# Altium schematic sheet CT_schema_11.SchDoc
size 677 x 458 mm
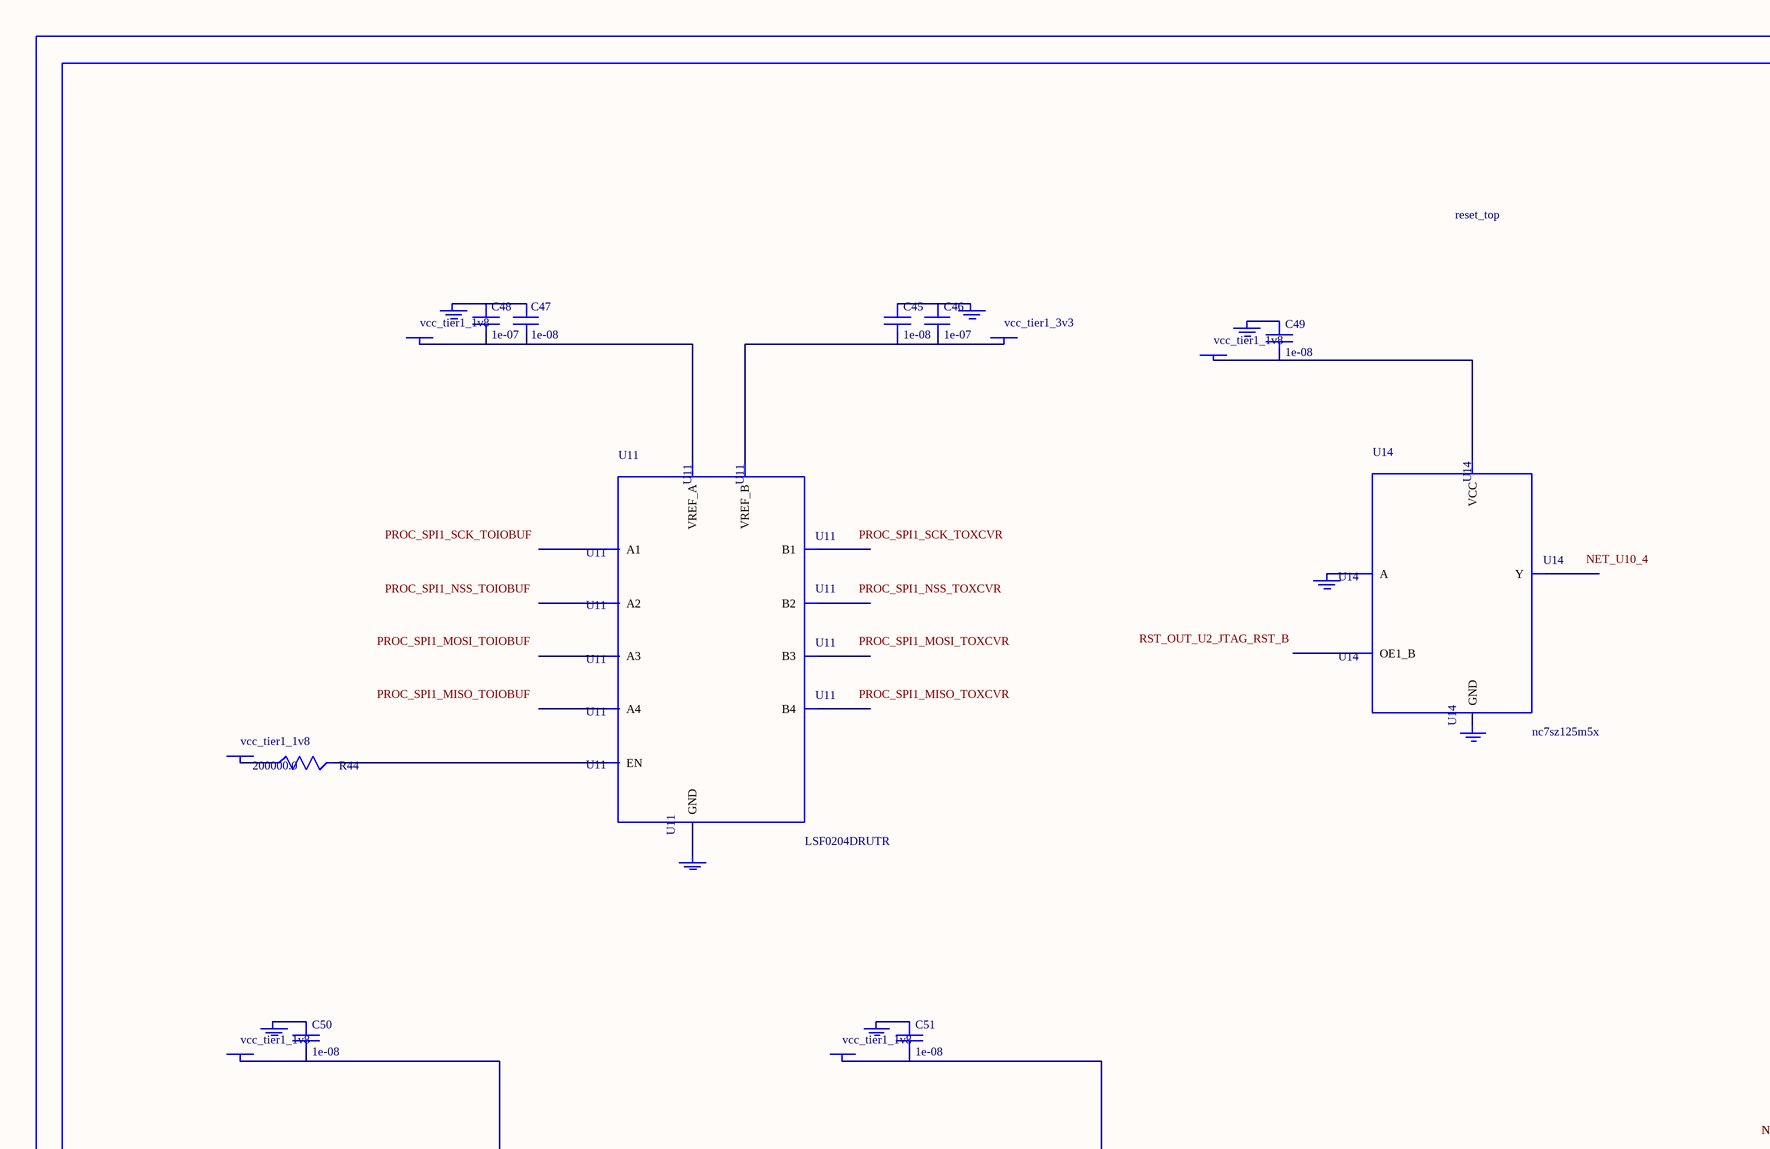
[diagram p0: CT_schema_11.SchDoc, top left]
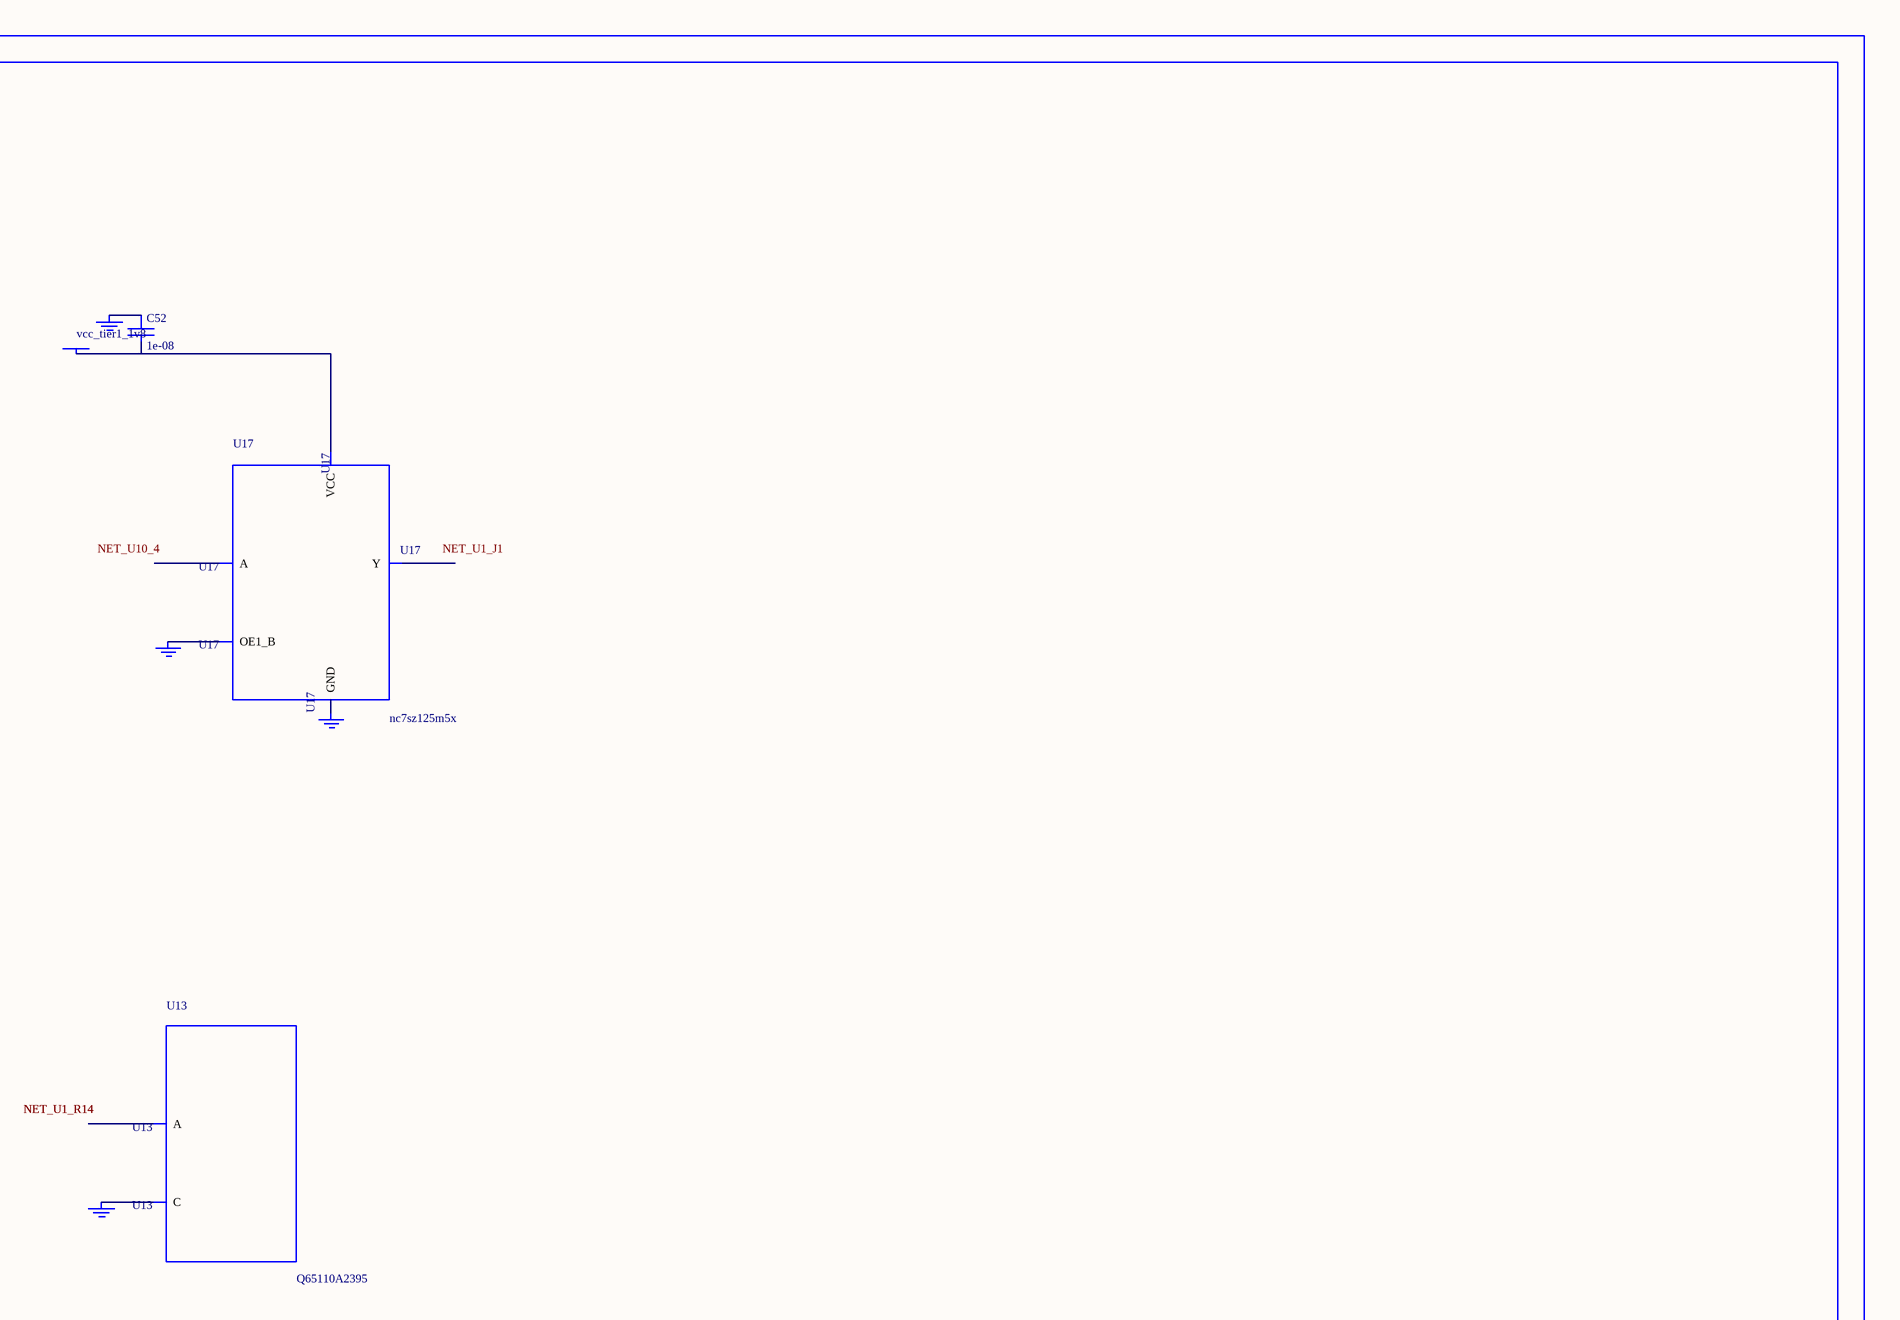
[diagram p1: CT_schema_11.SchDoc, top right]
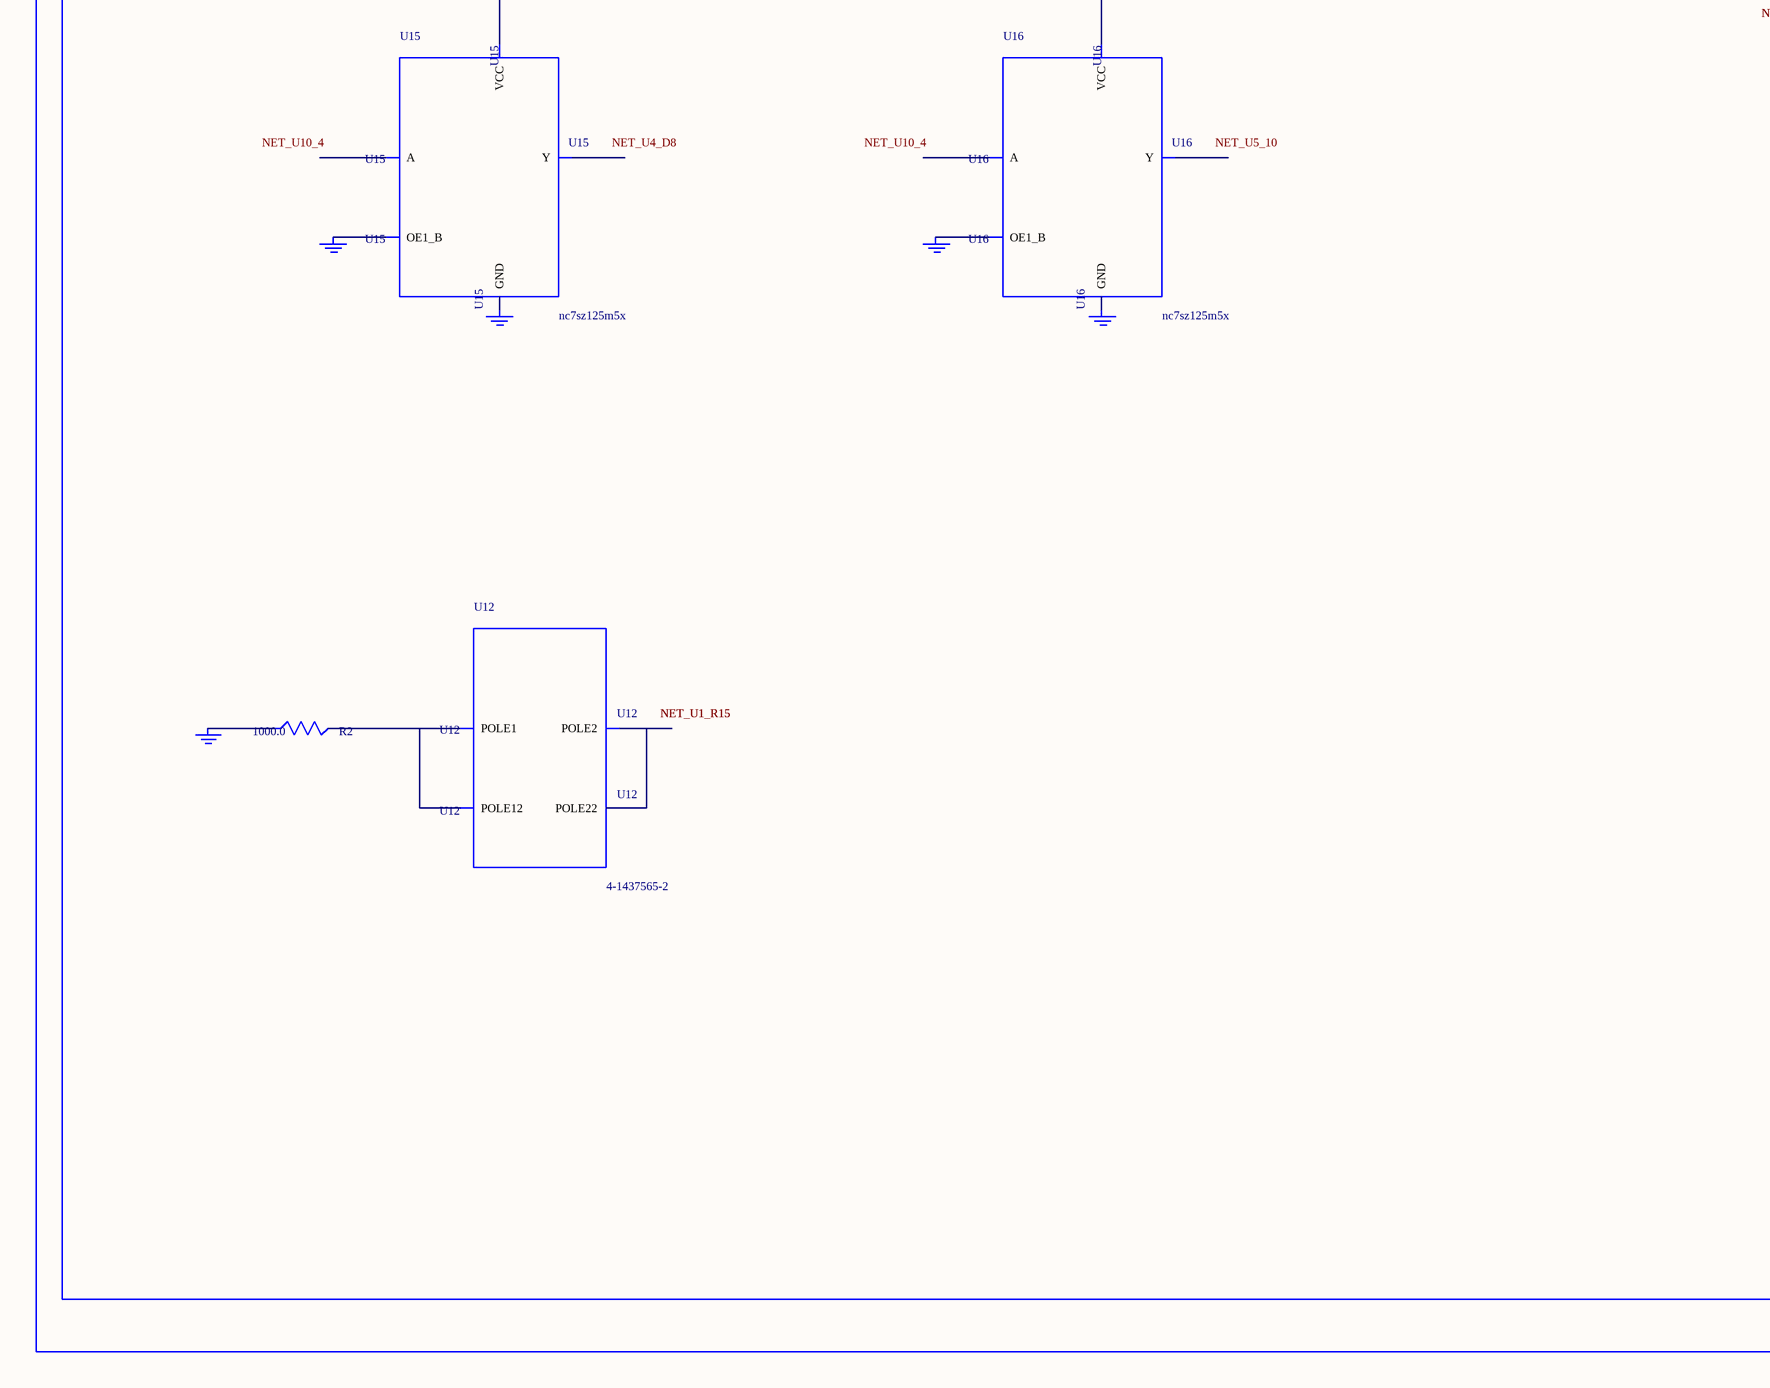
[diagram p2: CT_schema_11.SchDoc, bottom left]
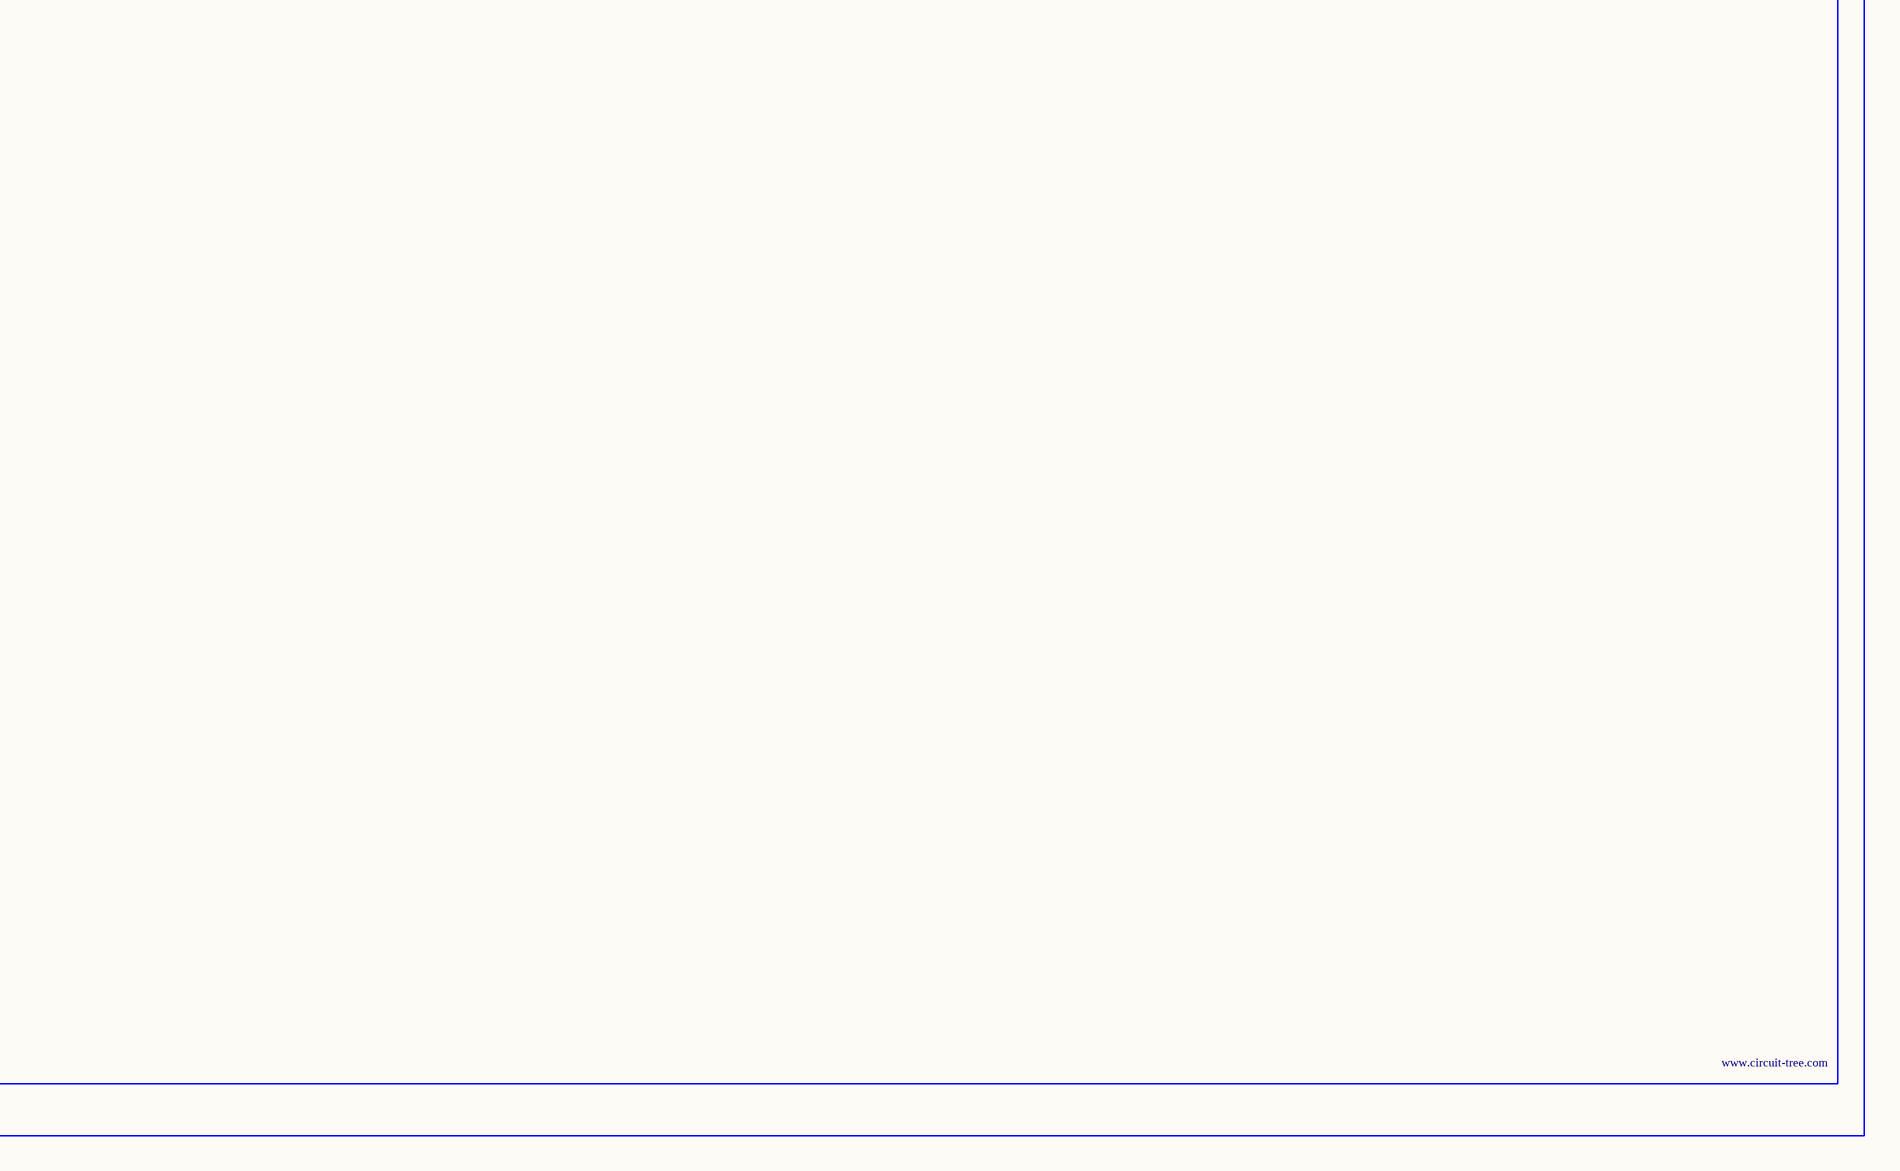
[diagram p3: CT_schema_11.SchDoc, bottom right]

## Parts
BORDER10  (no value)
C45  1e-08  [C0402]
C46  1e-07  [C0402]
C47  1e-08  [C0402]
C48  1e-07  [C0402]
C49  1e-08  [C0402]
C50  1e-08  [C0402]
C51  1e-08  [C0402]
C52  1e-08  [C0402]
GND_INSTANCE_10_0  (no value)
GND_INSTANCE_10_1  (no value)
GND_INSTANCE_10_2  (no value)
GND_INSTANCE_10_3  (no value)
GND_INSTANCE_10_4  (no value)
GND_INSTANCE_10_5  (no value)
GND_INSTANCE_10_6  (no value)
GND_INSTANCE_10_7  (no value)
GND_INSTANCE_10_8  (no value)
GND_INSTANCE_10_9  (no value)
GND_INSTANCE_10_10  (no value)
GND_INSTANCE_10_11  (no value)
GND_INSTANCE_10_12  (no value)
GND_INSTANCE_10_13  (no value)
GND_INSTANCE_10_14  (no value)
GND_INSTANCE_10_15  (no value)
GND_INSTANCE_10_16  (no value)
POWER_INSTANCE_10_0  vcc_tier1_1v8
POWER_INSTANCE_10_1  vcc_tier1_3v3
POWER_INSTANCE_10_2  vcc_tier1_1v8
POWER_INSTANCE_10_3  vcc_tier1_1v8
POWER_INSTANCE_10_4  vcc_tier1_1v8
POWER_INSTANCE_10_5  vcc_tier1_1v8
POWER_INSTANCE_10_6  vcc_tier1_1v8
R2  1000.0  [R0603]
R44  200000.0  [R0603]
U11  LSF0204DRUTR  [RUT0012A]
U12  4-1437565-2  [SW_4-1437565-2]
U13  Q65110A2395  [LGM67K-G1J2-24-Z]
U14  nc7sz125m5x  [NC7SZ125M5X]
U15  nc7sz125m5x  [NC7SZ125M5X]
U16  nc7sz125m5x  [NC7SZ125M5X]
U17  nc7sz125m5x  [NC7SZ125M5X]

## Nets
NetC45_1: C45.1 C46.1 GND_INSTANCE_10_1.0(GND)
NetC45_2: C45.2 C46.2 POWER_INSTANCE_10_1.0(PWR) U11.11(VREF_B)
NetC47_1: C47.1 C48.1 GND_INSTANCE_10_0.0(GND)
NetC47_2: C47.2 C48.2 POWER_INSTANCE_10_0.0(PWR) U11.1(VREF_A)
NetC49_1: C49.1 GND_INSTANCE_10_5.0(GND)
NetC49_2: C49.2 POWER_INSTANCE_10_3.0(PWR) U14.5(VCC)
NetC50_1: C50.1 GND_INSTANCE_10_8.0(GND)
NetC50_2: C50.2 POWER_INSTANCE_10_4.0(PWR) U15.5(VCC)
NetC51_1: C51.1 GND_INSTANCE_10_11.0(GND)
NetC51_2: C51.2 POWER_INSTANCE_10_5.0(PWR) U16.5(VCC)
NetC52_1: C52.1 GND_INSTANCE_10_14.0(GND)
NetC52_2: C52.2 POWER_INSTANCE_10_6.0(PWR) U17.5(VCC)
NetGND_INSTANCE_10_2_0: GND_INSTANCE_10_2.0(GND) U11.6(GND)
NetGND_INSTANCE_10_3_0: GND_INSTANCE_10_3.0(GND) R2.1
NetGND_INSTANCE_10_4_0: GND_INSTANCE_10_4.0(GND) U13.C
NetGND_INSTANCE_10_6_0: GND_INSTANCE_10_6.0(GND) U14.2(A)
NetGND_INSTANCE_10_7_0: GND_INSTANCE_10_7.0(GND) U14.3(GND)
NetGND_INSTANCE_10_9_0: GND_INSTANCE_10_9.0(GND) U15.1(OE1_B)
NetGND_INSTANCE_10_10_0: GND_INSTANCE_10_10.0(GND) U15.3(GND)
NetGND_INSTANCE_10_12_0: GND_INSTANCE_10_12.0(GND) U16.1(OE1_B)
NetGND_INSTANCE_10_13_0: GND_INSTANCE_10_13.0(GND) U16.3(GND)
NetGND_INSTANCE_10_15_0: GND_INSTANCE_10_15.0(GND) U17.1(OE1_B)
NetGND_INSTANCE_10_16_0: GND_INSTANCE_10_16.0(GND) U17.3(GND)
NetPOWER_INSTANCE_10_2_0: POWER_INSTANCE_10_2.0(PWR) R44.1
NetR2_2: R2.2 U12.1(POLE1) U12.2(POLE12)
NetR44_2: R44.2 U11.12(EN)
NetU12_3: U12.3(POLE2) U12.4(POLE22)

Not connected (* = marked no-connect by the designer): U11 2(A1) 3(A2) 4(A3) 5(A4) 7(B4) 8(B3) 9(B2) 10(B1); U13 A; U14 1(OE1_B) 4(Y); U15 2(A) 4(Y); U16 2(A) 4(Y); U17 2(A) 4(Y)

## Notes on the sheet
- Labels drawn without touching a wire or pin: NET_U1_J1, NET_U4_D8, NET_U5_10, NET_U10_4, PROC_SPI1_MISO_TOIOBUF, PROC_SPI1_MISO_TOXCVR, PROC_SPI1_MOSI_TOIOBUF, PROC_SPI1_MOSI_TOXCVR, PROC_SPI1_NSS_TOIOBUF, PROC_SPI1_NSS_TOXCVR, PROC_SPI1_SCK_TOIOBUF, PROC_SPI1_SCK_TOXCVR, RST_OUT_U2_JTAG_RST_B

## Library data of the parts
BORDER10 = BORDER_PAGE10
C45 C47 C49-C52 = C0402C103K3RAC
C46 C48 = C0402C104K3RACTU
GND_INSTANCE_10_0-GND_INSTANCE_10_16 = GND
POWER_INSTANCE_10_0-POWER_INSTANCE_10_6 = PWR
R2 = RC0603JR-071KL
R44 = RC0603JR-07200KL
